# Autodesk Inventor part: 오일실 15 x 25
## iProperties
IsCustomPart: 0
Created: 2015-10
Part Number: 오일실 15 x 25
Material: 고무
Description: 오일-실
Document SubType Name: Modeling
Standard: KS B 2804
Designer: mdu
Standards Organization: KS
Language: ko-KR
Size Designation: S - 15 25 7
Categories: <MemberInstance><Categories><Category DisplayName="샤프트 부품" InternalName="7f7aeb1f-a693-4053-b835-cee3144e0d98" Mnemonic="SHFT"><Category DisplayName="실링" Intern
Density: 0.93 g/cm^3
Author: mdu
